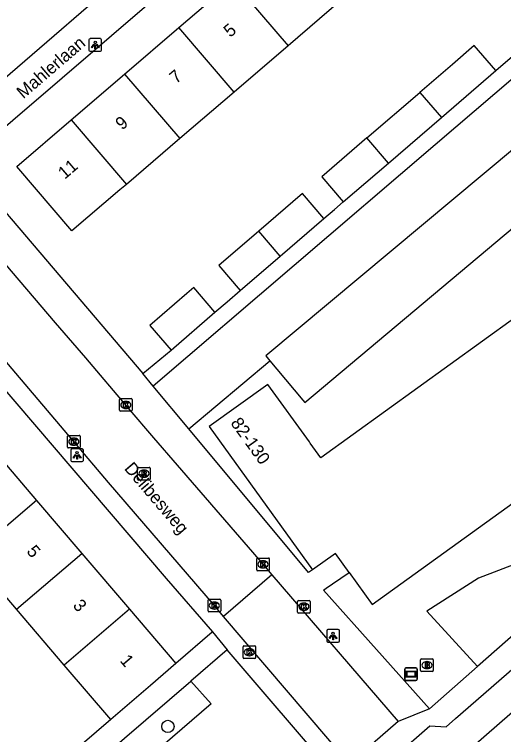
# Model space of a CAD drawing. Extents: x 159040 to 160094, y 381214 to 382518.
# Drawn here: x 159385.2 to 159423.9, y 381470.2 to 381527.2 of the extents above; entities that cross this region are included whole.
import ezdxf

# ---------------------------------------------------------------- set-up
doc = ezdxf.new("R2010")
doc.units = 0
for name, color, linetype in [('IMGEO_Boom', 7, 'Continuous'), ('IMGEO_Brandkraan', 7, 'Continuous'), ('IMGEO_Fietspad_gesloten', 7, 'Continuous'), ('IMGEO_Groenvoorziening', 7, 'Continuous'), ('IMGEO_Kolk', 7, 'Continuous'), ('IMGEO_Lichtpunt', 7, 'Continuous'), ('IMGEO_Openbare_ruimte_label', 7, 'Continuous'), ('IMGEO_Pand', 7, 'Continuous'), ('IMGEO_Pand_nummerreeks', 7, 'Continuous'), ('IMGEO_Parkeervlak_halfverhard', 7, 'Continuous'), ('IMGEO_Rijbaan_lokaal_halfverhard', 7, 'Continuous'), ('IMGEO_Rijbaan_lokaal_open', 7, 'Continuous'), ('IMGEO_Rioolput', 7, 'Continuous'), ('IMGEO_Straatnaambord', 7, 'Continuous'), ('IMGEO_Voetpad_open', 7, 'Continuous')]:
    doc.layers.add(name, color=color, linetype=linetype)

msp = doc.modelspace()

# ---------------------------------------------------------------- linework, layer by layer
at = {"layer": 'IMGEO_Boom'}
msp.add_circle((159397.343, 381470.812), 0.489, dxfattribs=at)
at = {"layer": 'IMGEO_Brandkraan'}
for p, q in [((159417.366, 381475.239), (159417.366, 381476.091)), ((159417.441, 381476.165), (159418.293, 381476.165)), ((159417.854, 381475.945), (159417.879, 381475.945)), ((159418.367, 381476.091), (159418.367, 381475.239)), ((159418.293, 381475.165), (159417.441, 381475.165)), ((159417.877, 381475.385), (159417.852, 381475.385))]:
    msp.add_line(p, q, dxfattribs=at)
for points in [[(159417.366, 381475.239), (159417.366, 381476.091)], [(159417.441, 381476.165), (159418.293, 381476.165)], [(159417.714, 381475.865), (159417.714, 381475.465), (159417.927, 381475.465)], [(159417.945, 381475.865), (159417.714, 381475.865)], [(159417.893, 381475.784), (159417.839, 381475.784), (159417.839, 381475.708)], [(159417.839, 381475.708), (159417.892, 381475.708)], [(159417.901, 381475.632), (159417.839, 381475.632), (159417.839, 381475.551)], [(159418.367, 381476.091), (159418.367, 381475.239)], [(159418.293, 381475.165), (159417.441, 381475.165)], [(159417.839, 381475.551), (159417.901, 381475.551)]]:
    msp.add_lwpolyline(points, dxfattribs=at)
for centre, radius, start, end in [((159417.443, 381476.089), 0.0765, 91.552, 178.448), ((159417.443, 381476.089), 0.0765, 91.552, 178.448), ((159417.894, 381475.746), 0.0379, 267.8285, 90.9355), ((159417.902, 381475.591), 0.0404, 269.8759, 90.5077), ((159417.949, 381475.72), 0.145, 59.4692, 91.5367), ((159417.974, 381475.767), 0.0922, 285.5137, 58.1501), ((159417.979, 381475.575), 0.105, 301.3115, 78.989), ((159418.291, 381476.089), 0.0765, 1.552, 88.448), ((159418.291, 381476.089), 0.0765, 1.552, 88.448), ((159417.443, 381475.241), 0.0765, 181.552, 268.448), ((159417.443, 381475.241), 0.0765, 181.552, 268.448), ((159417.933, 381475.716), 0.251, 268.6676, 293.5347), ((159418.291, 381475.241), 0.0765, 271.552, 358.448), ((159418.291, 381475.241), 0.0765, 271.552, 358.448)]:
    msp.add_arc(centre, radius, start, end, dxfattribs=at)
for centre, major_axis, ratio, start_param, end_param in [((159417.853, 381475.665), (-0.387, 0.002), 0.722429, 4.712389, 7.853982), ((159417.878, 381475.665), (-0.39, 0.002), 0.717154, 1.570796, 4.712389)]:
    msp.add_ellipse(centre, major_axis=major_axis, ratio=ratio, start_param=start_param, end_param=end_param, dxfattribs=at)
at = {"layer": 'IMGEO_Fietspad_gesloten'}
for points in [[(159397.846, 381453.215), (159409.946, 381463.74), (159418.101, 381470.859), (159419.379, 381470.789), (159420.124, 381471.433), (159425.386, 381476.018), (159432.65, 381482.499), (159450.596, 381498.844), (159457.179, 381504.954)], [(159424.652, 381471.931), (159408.144, 381457.558)]]:
    msp.add_lwpolyline(points, dxfattribs=at)
at = {"layer": 'IMGEO_Groenvoorziening'}
for points in [[(159428.197, 381481.125), (159426.243, 381483.67), (159425.124, 381483.768), (159421.943, 381482.542), (159417.844, 381479.941), (159421.861, 381475.546)], [(159399.15, 381474.403), (159400.78, 381472.608), (159386.592, 381460.368), (159385.077, 381462.313)]]:
    msp.add_lwpolyline(points, dxfattribs=at)
at = {"layer": 'IMGEO_Kolk'}
for p, q in [((159393.587, 381496.769), (159394.439, 381496.769)), ((159393.512, 381495.843), (159393.512, 381496.695)), ((159394, 381496.549), (159394.025, 381496.549)), ((159394.513, 381496.695), (159394.513, 381495.843)), ((159394.439, 381495.769), (159393.587, 381495.769)), ((159394.023, 381495.989), (159393.998, 381495.989)), ((159389.392, 381492.934), (159389.392, 381493.786)), ((159389.467, 381493.86), (159390.319, 381493.86)), ((159389.88, 381493.64), (159389.905, 381493.64)), ((159390.393, 381493.786), (159390.393, 381492.934)), ((159390.319, 381492.86), (159389.467, 381492.86)), ((159389.903, 381493.08), (159389.878, 381493.08)), ((159404.377, 381483.219), (159404.377, 381484.071)), ((159404.452, 381484.145), (159405.304, 381484.145)), ((159404.865, 381483.925), (159404.89, 381483.925)), ((159405.378, 381484.071), (159405.378, 381483.219)), ((159405.304, 381483.145), (159404.452, 381483.145)), ((159404.888, 381483.365), (159404.863, 381483.365)), ((159400.522, 381479.957), (159400.522, 381480.809)), ((159400.597, 381480.883), (159401.449, 381480.883)), ((159401.523, 381480.809), (159401.523, 381479.957)), ((159407.693, 381480.79), (159408.545, 381480.79)), ((159401.01, 381480.663), (159401.035, 381480.663)), ((159407.618, 381479.864), (159407.618, 381480.716)), ((159408.106, 381480.57), (159408.131, 381480.57)), ((159408.619, 381480.716), (159408.619, 381479.864)), ((159401.449, 381479.883), (159400.597, 381479.883)), ((159401.033, 381480.103), (159401.008, 381480.103)), ((159408.545, 381479.79), (159407.693, 381479.79)), ((159408.129, 381480.01), (159408.104, 381480.01)), ((159403.294, 381476.263), (159403.294, 381477.115)), ((159403.369, 381477.189), (159404.221, 381477.189)), ((159403.782, 381476.969), (159403.807, 381476.969)), ((159404.295, 381477.115), (159404.295, 381476.263)), ((159403.805, 381476.409), (159403.78, 381476.409)), ((159404.221, 381476.189), (159403.369, 381476.189))]:
    msp.add_line(p, q, dxfattribs=at)
for points in [[(159393.587, 381496.769), (159394.439, 381496.769)], [(159393.512, 381495.843), (159393.512, 381496.695)], [(159393.833, 381496.469), (159393.956, 381496.469), (159393.956, 381496.318), (159394.086, 381496.469), (159394.25, 381496.469), (159394.104, 381496.318), (159394.257, 381496.069), (159394.105, 381496.069), (159394.02, 381496.233), (159393.956, 381496.166), (159393.956, 381496.069), (159393.833, 381496.069), (159393.833, 381496.469)], [(159394.513, 381496.695), (159394.513, 381495.843)], [(159394.439, 381495.769), (159393.587, 381495.769)], [(159389.392, 381492.934), (159389.392, 381493.786)], [(159389.467, 381493.86), (159390.319, 381493.86)], [(159389.713, 381493.56), (159389.836, 381493.56), (159389.836, 381493.409), (159389.966, 381493.56), (159390.13, 381493.56), (159389.984, 381493.409), (159390.137, 381493.16), (159389.985, 381493.16), (159389.9, 381493.324), (159389.836, 381493.257), (159389.836, 381493.16), (159389.713, 381493.16), (159389.713, 381493.56)], [(159390.393, 381493.786), (159390.393, 381492.934)], [(159390.319, 381492.86), (159389.467, 381492.86)], [(159404.377, 381483.219), (159404.377, 381484.071)], [(159404.452, 381484.145), (159405.304, 381484.145)], [(159404.698, 381483.845), (159404.821, 381483.845), (159404.821, 381483.694), (159404.951, 381483.845), (159405.115, 381483.845), (159404.969, 381483.694), (159405.122, 381483.445), (159404.97, 381483.445), (159404.885, 381483.609), (159404.821, 381483.542), (159404.821, 381483.445), (159404.698, 381483.445), (159404.698, 381483.845)], [(159405.378, 381484.071), (159405.378, 381483.219)], [(159405.304, 381483.145), (159404.452, 381483.145)], [(159400.522, 381479.957), (159400.522, 381480.809)], [(159400.597, 381480.883), (159401.449, 381480.883)], [(159401.523, 381480.809), (159401.523, 381479.957)], [(159407.693, 381480.79), (159408.545, 381480.79)], [(159400.843, 381480.583), (159400.966, 381480.583), (159400.966, 381480.432), (159401.096, 381480.583), (159401.26, 381480.583), (159401.114, 381480.432), (159401.267, 381480.183), (159401.115, 381480.183), (159401.03, 381480.347), (159400.966, 381480.28), (159400.966, 381480.183), (159400.843, 381480.183), (159400.843, 381480.583)], [(159407.618, 381479.864), (159407.618, 381480.716)], [(159407.939, 381480.49), (159408.062, 381480.49), (159408.062, 381480.339), (159408.192, 381480.49), (159408.356, 381480.49), (159408.21, 381480.339), (159408.363, 381480.09), (159408.211, 381480.09), (159408.126, 381480.254), (159408.062, 381480.187), (159408.062, 381480.09), (159407.939, 381480.09), (159407.939, 381480.49)], [(159408.619, 381480.716), (159408.619, 381479.864)], [(159401.449, 381479.883), (159400.597, 381479.883)], [(159408.545, 381479.79), (159407.693, 381479.79)], [(159403.294, 381476.263), (159403.294, 381477.115)], [(159403.369, 381477.189), (159404.221, 381477.189)], [(159403.615, 381476.889), (159403.738, 381476.889), (159403.738, 381476.738), (159403.868, 381476.889), (159404.032, 381476.889), (159403.886, 381476.738), (159404.039, 381476.489), (159403.887, 381476.489), (159403.802, 381476.653), (159403.738, 381476.586), (159403.738, 381476.489), (159403.615, 381476.489), (159403.615, 381476.889)], [(159404.295, 381477.115), (159404.295, 381476.263)], [(159404.221, 381476.189), (159403.369, 381476.189)]]:
    msp.add_lwpolyline(points, dxfattribs=at)
for centre, start, end in [((159393.589, 381496.693), 91.552, 178.448), ((159393.589, 381496.693), 91.552, 178.448), ((159394.437, 381496.693), 1.552, 88.448), ((159394.437, 381496.693), 1.552, 88.448), ((159393.589, 381495.845), 181.552, 268.448), ((159393.589, 381495.845), 181.552, 268.448), ((159394.437, 381495.845), 271.552, 358.448), ((159394.437, 381495.845), 271.552, 358.448), ((159389.469, 381493.784), 91.552, 178.448), ((159389.469, 381493.784), 91.552, 178.448), ((159390.317, 381493.784), 1.552, 88.448), ((159390.317, 381493.784), 1.552, 88.448), ((159389.469, 381492.936), 181.552, 268.448), ((159389.469, 381492.936), 181.552, 268.448), ((159390.317, 381492.936), 271.552, 358.448), ((159390.317, 381492.936), 271.552, 358.448), ((159404.454, 381484.069), 91.552, 178.448), ((159404.454, 381484.069), 91.552, 178.448), ((159405.302, 381484.069), 1.552, 88.448), ((159405.302, 381484.069), 1.552, 88.448), ((159404.454, 381483.221), 181.552, 268.448), ((159404.454, 381483.221), 181.552, 268.448), ((159405.302, 381483.221), 271.552, 358.448), ((159405.302, 381483.221), 271.552, 358.448), ((159400.599, 381480.807), 91.552, 178.448), ((159400.599, 381480.807), 91.552, 178.448), ((159401.447, 381480.807), 1.552, 88.448), ((159401.447, 381480.807), 1.552, 88.448), ((159407.695, 381480.714), 91.552, 178.448), ((159407.695, 381480.714), 91.552, 178.448), ((159408.543, 381480.714), 1.552, 88.448), ((159408.543, 381480.714), 1.552, 88.448), ((159400.599, 381479.959), 181.552, 268.448), ((159400.599, 381479.959), 181.552, 268.448), ((159401.447, 381479.959), 271.552, 358.448), ((159401.447, 381479.959), 271.552, 358.448), ((159407.695, 381479.866), 181.552, 268.448), ((159407.695, 381479.866), 181.552, 268.448), ((159408.543, 381479.866), 271.552, 358.448), ((159408.543, 381479.866), 271.552, 358.448), ((159403.371, 381477.113), 91.552, 178.448), ((159403.371, 381477.113), 91.552, 178.448), ((159404.219, 381477.113), 1.552, 88.448), ((159404.219, 381477.113), 1.552, 88.448), ((159403.371, 381476.265), 181.552, 268.448), ((159403.371, 381476.265), 181.552, 268.448), ((159404.219, 381476.265), 271.552, 358.448), ((159404.219, 381476.265), 271.552, 358.448)]:
    msp.add_arc(centre, 0.0765, start, end, dxfattribs=at)
for centre, major_axis, ratio, start_param, end_param in [((159393.999, 381496.269), (-0.387, 0.002), 0.722429, 4.712389, 7.853982), ((159394.024, 381496.269), (-0.39, 0.002), 0.717154, 1.570796, 4.712389), ((159389.879, 381493.36), (-0.387, 0.002), 0.722429, 4.712389, 7.853982), ((159389.904, 381493.36), (-0.39, 0.002), 0.717154, 1.570796, 4.712389), ((159404.864, 381483.645), (-0.387, 0.002), 0.722429, 4.712389, 7.853982), ((159404.889, 381483.645), (-0.39, 0.002), 0.717154, 1.570796, 4.712389), ((159401.009, 381480.383), (-0.387, 0.002), 0.722429, 4.712389, 7.853982), ((159401.034, 381480.383), (-0.39, 0.002), 0.717154, 1.570796, 4.712389), ((159408.105, 381480.29), (-0.387, 0.002), 0.722429, 4.712389, 7.853982), ((159408.13, 381480.29), (-0.39, 0.002), 0.717154, 1.570796, 4.712389), ((159403.781, 381476.689), (-0.387, 0.002), 0.722429, 4.712389, 7.853982), ((159403.806, 381476.689), (-0.39, 0.002), 0.717154, 1.570796, 4.712389)]:
    msp.add_ellipse(centre, major_axis=major_axis, ratio=ratio, start_param=start_param, end_param=end_param, dxfattribs=at)
at = {"layer": 'IMGEO_Lichtpunt'}
for p, q in [((159391.992, 381525.272), (159391.184, 381525.272)), ((159391.992, 381525.272), (159391.184, 381525.272)), ((159391.09, 381525.177), (159391.09, 381524.37)), ((159391.09, 381525.177), (159391.09, 381524.37)), ((159392.086, 381524.37), (159392.086, 381525.177)), ((159392.086, 381524.37), (159392.086, 381525.177)), ((159391.184, 381524.276), (159391.992, 381524.276)), ((159391.184, 381524.276), (159391.992, 381524.276)), ((159390.549, 381492.782), (159389.741, 381492.782)), ((159390.549, 381492.782), (159389.741, 381492.782)), ((159389.647, 381492.687), (159389.647, 381491.88)), ((159389.647, 381492.687), (159389.647, 381491.88)), ((159390.643, 381491.88), (159390.643, 381492.687)), ((159390.643, 381491.88), (159390.643, 381492.687)), ((159389.741, 381491.786), (159390.549, 381491.786)), ((159389.741, 381491.786), (159390.549, 381491.786)), ((159410.831, 381478.482), (159410.023, 381478.482)), ((159410.831, 381478.482), (159410.023, 381478.482)), ((159409.929, 381478.387), (159409.929, 381477.58)), ((159409.929, 381478.387), (159409.929, 381477.58)), ((159410.925, 381477.58), (159410.925, 381478.387)), ((159410.925, 381477.58), (159410.925, 381478.387)), ((159410.023, 381477.486), (159410.831, 381477.486)), ((159410.023, 381477.486), (159410.831, 381477.486))]:
    msp.add_line(p, q, dxfattribs=at)
for points in [[(159391.464, 381524.841), (159391.503, 381524.813), (159391.315, 381524.551), (159391.277, 381524.578), (159391.464, 381524.841)], [(159391.566, 381524.793), (159391.613, 381524.793), (159391.613, 381524.471), (159391.566, 381524.471), (159391.566, 381524.793)], [(159391.676, 381524.813), (159391.714, 381524.84), (159391.901, 381524.578), (159391.862, 381524.55), (159391.676, 381524.813)], [(159390.021, 381492.351), (159390.06, 381492.323), (159389.872, 381492.061), (159389.834, 381492.088), (159390.021, 381492.351)], [(159390.123, 381492.303), (159390.17, 381492.303), (159390.17, 381491.981), (159390.123, 381491.981), (159390.123, 381492.303)], [(159390.233, 381492.323), (159390.271, 381492.35), (159390.458, 381492.088), (159390.419, 381492.06), (159390.233, 381492.323)], [(159410.303, 381478.051), (159410.342, 381478.023), (159410.154, 381477.761), (159410.116, 381477.788), (159410.303, 381478.051)], [(159410.405, 381478.003), (159410.452, 381478.003), (159410.452, 381477.681), (159410.405, 381477.681), (159410.405, 381478.003)], [(159410.515, 381478.023), (159410.553, 381478.05), (159410.74, 381477.788), (159410.701, 381477.76), (159410.515, 381478.023)]]:
    msp.add_lwpolyline(points, dxfattribs=at)
for centre in [(159391.589, 381524.975), (159390.146, 381492.485), (159410.428, 381478.185)]:
    msp.add_circle(centre, 0.0994, dxfattribs=at)
for centre, start, end in [((159391.184, 381525.177), 90, 180), ((159391.184, 381525.177), 90, 180), ((159391.992, 381525.177), 0, 90), ((159391.992, 381525.177), 0, 90), ((159391.184, 381524.37), 180, 270), ((159391.184, 381524.37), 180, 270), ((159391.992, 381524.37), 270, 0), ((159391.992, 381524.37), 270, 360), ((159389.741, 381492.687), 90, 180), ((159389.741, 381492.687), 90, 180), ((159390.549, 381492.687), 0, 90), ((159390.549, 381492.687), 0, 90), ((159389.741, 381491.88), 180, 270), ((159389.741, 381491.88), 180, 270), ((159390.549, 381491.88), 270, 0), ((159390.549, 381491.88), 270, 360), ((159410.023, 381478.387), 90, 180), ((159410.023, 381478.387), 90, 180), ((159410.831, 381478.387), 0, 90), ((159410.831, 381478.387), 0, 90), ((159410.023, 381477.58), 180, 270), ((159410.023, 381477.58), 180, 270), ((159410.831, 381477.58), 270, 0), ((159410.831, 381477.58), 270, 360)]:
    msp.add_arc(centre, 0.0946, start, end, dxfattribs=at)
at = {"layer": 'IMGEO_Pand'}
for points in [[(159398.206, 381526.153), (159402.482, 381529.816)], [(159402.482, 381529.816), (159406.858, 381524.709)], [(159411.064, 381528.312), (159406.858, 381524.709)], [(159393.899, 381522.464), (159398.206, 381526.153)], [(159402.582, 381521.045), (159398.206, 381526.153)], [(159406.858, 381524.709), (159402.582, 381521.045)], [(159423.321, 381522.739), (159421.617, 381524.72), (159419.893, 381523.238), (159417.312, 381521.019)], [(159389.675, 381518.845), (159393.899, 381522.464)], [(159393.899, 381522.464), (159398.275, 381517.356)], [(159419.012, 381519.034), (159423.321, 381522.739)], [(159402.582, 381521.045), (159398.275, 381517.356)], [(159413.114, 381517.408), (159417.312, 381521.019)], [(159417.312, 381521.019), (159419.012, 381519.034)], [(159414.814, 381515.424), (159419.012, 381519.034)], [(159394.051, 381513.737), (159393.538, 381513.297), (159389.74, 381510.044), (159385.364, 381515.152), (159389.675, 381518.845)], [(159389.675, 381518.845), (159394.051, 381513.737)], [(159398.275, 381517.356), (159394.051, 381513.737)], [(159413.114, 381517.408), (159409.538, 381514.333), (159411.238, 381512.348)], [(159414.814, 381515.424), (159413.114, 381517.408)], [(159411.238, 381512.348), (159414.814, 381515.424)], [(159443.672, 381502.214), (159445.674, 381503.658), (159438.771, 381513.228), (159437.641, 381512.413), (159409.461, 381492.085), (159408.621, 381493.25), (159408.548, 381493.351), (159405.27, 381497.898), (159400.619, 381494.55), (159408.785, 381483.207)], [(159409.705, 381511.03), (159408.005, 381513.015), (159404.544, 381510.038)], [(159406.244, 381508.054), (159409.705, 381511.03)], [(159404.544, 381510.038), (159401.369, 381507.308), (159403.069, 381505.323)], [(159406.244, 381508.054), (159404.544, 381510.038)], [(159403.069, 381505.323), (159406.244, 381508.054)], [(159401.07, 381503.604), (159399.391, 381505.565), (159398.849, 381505.099), (159395.909, 381502.571), (159397.592, 381500.614)], [(159397.592, 381500.614), (159401.07, 381503.604)], [(159383.349, 381492.893), (159386.93, 381488.708)], [(159411.698, 381483.002), (159413.525, 381480.468), (159429.891, 381492.273)], [(159386.93, 381488.708), (159381.766, 381484.29)], [(159386.93, 381488.708), (159390.522, 381484.51)], [(159385.353, 381480.089), (159381.766, 381484.29)], [(159385.353, 381480.089), (159390.522, 381484.51)], [(159390.522, 381484.51), (159394.307, 381480.086)], [(159411.698, 381483.002), (159410.617, 381484.502), (159408.785, 381483.207)], [(159389.134, 381475.66), (159385.353, 381480.089)], [(159394.307, 381480.086), (159389.134, 381475.66)], [(159394.307, 381480.086), (159397.979, 381475.794)], [(159392.811, 381471.352), (159389.134, 381475.66)], [(159397.979, 381475.794), (159395.967, 381474.065), (159392.811, 381471.352)]]:
    msp.add_lwpolyline(points, dxfattribs=at)
at = {"layer": 'IMGEO_Parkeervlak_halfverhard'}
msp.add_lwpolyline([(159405.429, 381499.757), (159405.971, 381499.107), (159408.027, 381496.644), (159408.178, 381496.463), (159435.656, 381519.493), (159435.016, 381520.142), (159432.318, 381522.873)], dxfattribs=at)
at = {"layer": 'IMGEO_Rijbaan_lokaal_halfverhard'}
for points in [[(159432.643, 381523.144), (159429.94, 381525.7), (159429.42, 381526.192), (159418.516, 381516.866), (159396.185, 381497.766)], [(159432.318, 381522.873), (159405.096, 381500.156), (159405.429, 381499.757)], [(159398.993, 381494.387), (159405.429, 381499.757)], [(159398.993, 381494.387), (159396.185, 381497.766)]]:
    msp.add_lwpolyline(points, dxfattribs=at)
at = {"layer": 'IMGEO_Rijbaan_lokaal_open'}
for points in [[(159412.409, 381542.277), (159381.123, 381515.43)], [(159359.079, 381537.039), (159361.379, 381534.296), (159376.214, 381517.042), (159376.8, 381516.357), (159379.3, 381513.434), (159388.415, 381502.775), (159390.802, 381500), (159394.17, 381496.049), (159396.211, 381493.655), (159398.069, 381491.509), (159404.878, 381483.645), (159405.572, 381482.813)], [(159379.202, 381517.668), (159392.797, 381529.398)], [(159401.74, 381479.524), (159401.023, 381480.383), (159392.642, 381490.134), (159389.868, 381493.391), (159384.255, 381500), (159381.439, 381503.315), (159380.301, 381504.635)], [(159405.572, 381482.813), (159401.74, 381479.524)], [(159405.572, 381482.813), (159415.578, 381471.202)], [(159411.724, 381467.861), (159401.74, 381479.524)], [(159415.578, 381471.202), (159411.724, 381467.861)]]:
    msp.add_lwpolyline(points, dxfattribs=at)
at = {"layer": 'IMGEO_Rioolput'}
for p, q in [((159394.943, 381490.398), (159394.943, 381491.25)), ((159395.018, 381491.324), (159395.87, 381491.324)), ((159395.431, 381491.104), (159395.456, 381491.104)), ((159395.944, 381491.25), (159395.944, 381490.398)), ((159395.454, 381490.544), (159395.429, 381490.544)), ((159395.87, 381490.324), (159395.018, 381490.324))]:
    msp.add_line(p, q, dxfattribs=at)
for points in [[(159394.943, 381490.398), (159394.943, 381491.25)], [(159395.018, 381491.324), (159395.87, 381491.324)], [(159395.944, 381491.25), (159395.944, 381490.398)], [(159395.532, 381491.022), (159395.28, 381491.024), (159395.28, 381490.624)], [(159395.28, 381490.624), (159395.404, 381490.624), (159395.404, 381490.786), (159395.415, 381490.786)], [(159395.458, 381490.943), (159395.404, 381490.943), (159395.404, 381490.862)], [(159395.404, 381490.862), (159395.456, 381490.862)], [(159395.462, 381490.757), (159395.533, 381490.624), (159395.673, 381490.624), (159395.608, 381490.75)], [(159395.87, 381490.324), (159395.018, 381490.324)]]:
    msp.add_lwpolyline(points, dxfattribs=at)
for centre, radius, start, end in [((159395.02, 381491.248), 0.0765, 91.552, 178.448), ((159395.02, 381491.248), 0.0765, 91.552, 178.448), ((159395.868, 381491.248), 0.0765, 1.552, 88.448), ((159395.868, 381491.248), 0.0765, 1.552, 88.448), ((159395.414, 381490.733), 0.0533, 26.0293, 88.6989), ((159395.44, 381491.051), 0.19, 274.7715, 282.9687), ((159395.464, 381490.847), 0.0964, 77.0061, 93.1865), ((159395.478, 381490.904), 0.0378, 276.6634, 79.6772), ((159395.531, 381490.912), 0.109, 350.3612, 89.416), ((159395.529, 381490.912), 0.112, 277.5842, 350.9817), ((159395.513, 381490.697), 0.108, 29.5134, 73.7905), ((159395.02, 381490.4), 0.0765, 181.552, 268.448), ((159395.02, 381490.4), 0.0765, 181.552, 268.448), ((159395.868, 381490.4), 0.0765, 271.552, 358.448), ((159395.868, 381490.4), 0.0765, 271.552, 358.448)]:
    msp.add_arc(centre, radius, start, end, dxfattribs=at)
for centre, major_axis, ratio, start_param, end_param in [((159395.43, 381490.824), (-0.387, 0.002), 0.722429, 4.712389, 7.853982), ((159395.455, 381490.824), (-0.39, 0.002), 0.717154, 1.570796, 4.712389)]:
    msp.add_ellipse(centre, major_axis=major_axis, ratio=ratio, start_param=start_param, end_param=end_param, dxfattribs=at)
at = {"layer": 'IMGEO_Straatnaambord'}
for p, q in [((159416.103, 381474.557), (159416.103, 381475.357)), ((159416.103, 381475.357), (159416.103, 381474.557)), ((159416.203, 381475.457), (159416.993, 381475.457)), ((159416.993, 381475.457), (159416.203, 381475.457)), ((159417.093, 381475.357), (159417.093, 381474.557)), ((159417.093, 381474.557), (159417.093, 381475.357)), ((159416.993, 381474.457), (159416.203, 381474.457)), ((159416.203, 381474.457), (159416.993, 381474.457))]:
    msp.add_line(p, q, dxfattribs=at)
for points in [[(159416.204, 381475.189), (159416.992, 381475.189), (159416.992, 381474.725), (159416.204, 381474.725), (159416.204, 381475.189)], [(159416.269, 381475.124), (159416.269, 381474.79), (159416.927, 381474.79), (159416.927, 381475.124), (159416.269, 381475.124)]]:
    msp.add_lwpolyline(points, dxfattribs=at)
for centre, start, end in [((159416.203, 381475.357), 90, 180), ((159416.203, 381475.357), 90, 180), ((159416.993, 381475.357), 0, 90), ((159416.993, 381475.357), 360, 90), ((159416.203, 381474.557), 180, 270), ((159416.203, 381474.557), 180, 270), ((159416.993, 381474.557), 270, 0), ((159416.993, 381474.557), 270, 0)]:
    msp.add_arc(centre, 0.1, start, end, dxfattribs=at)
at = {"layer": 'IMGEO_Voetpad_open'}
for points in [[(159423.321, 381522.739), (159428.428, 381527.13), (159419.794, 381535.294), (159412.409, 381542.277)], [(159381.123, 381515.43), (159395.359, 381498.763)], [(159409.705, 381511.03), (159410.544, 381511.751), (159411.238, 381512.348)], [(159401.07, 381503.604), (159402.027, 381504.427), (159403.069, 381505.323)], [(159379.225, 381503.503), (159382.243, 381500), (159397.195, 381482.524), (159400.885, 381478.302)], [(159395.359, 381498.763), (159397.592, 381500.614)], [(159396.185, 381497.766), (159395.359, 381498.763)], [(159408.785, 381483.207), (159408.491, 381483.004), (159398.993, 381494.387)], [(159418.061, 381472.201), (159409.67, 381481.596), (159409.881, 381481.754), (159410.381, 381482.105), (159411.698, 381483.002)], [(159428.197, 381481.125), (159421.861, 381475.546)], [(159400.885, 381478.302), (159400.855, 381478.267), (159397.979, 381475.794)], [(159400.885, 381478.302), (159402.03, 381476.877)], [(159402.03, 381476.877), (159399.15, 381474.403)], [(159410.608, 381466.883), (159402.03, 381476.877)], [(159421.861, 381475.546), (159418.061, 381472.201)], [(159385.077, 381462.313), (159399.15, 381474.403)], [(159418.061, 381472.201), (159415.578, 381471.202)], [(159392.811, 381471.352), (159385.828, 381465.349)]]:
    msp.add_lwpolyline(points, dxfattribs=at)

# ---------------------------------------------------------------- texts
at = {"layer": 'IMGEO_Openbare_ruimte_label'}
for s, rotation, p in [('Mahlerlaan', 40.7442, (159385.887, 381520.465)), ('Delibesweg', 310.4584, (159393.835, 381491.208))]:
    msp.add_text(s, height=1, rotation=rotation, dxfattribs=at).set_placement(p)
at = {"layer": 'IMGEO_Pand_nummerreeks'}
for s, rotation, p in [('5', 40.585, (159402.284, 381525.327)), ('7', 40.585, (159398, 381521.657)), ('9', 40.585, (159393.715, 381517.987)), ('11', 40.585, (159389.168, 381514.092)), ('82-130', 305.7524, (159402.268, 381494.827)), ('5', 310.5497, (159386.094, 381484.641)), ('3', 310.5497, (159389.759, 381480.357)), ('1', 310.5497, (159393.498, 381475.988))]:
    msp.add_text(s, height=1, rotation=rotation, dxfattribs=at).set_placement(p)

doc.saveas('drawing.dxf')
